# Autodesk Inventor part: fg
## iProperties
Shininess: 64.0
Length Units: 11269
Angle Units: 11279
Time Units: 11290
Mass Units: 11283
Length Display Precision: 3
Angle Display Precision: 2
Compacted: True
Part Number: fg
Document SubType Name: Modeling
Created: 2004-12
Designer: Administrator
Manufacturer: Standard
Standards Organization: Custom
Material: Aluminum-6061-AHC
Density: 0.0
Volumn: 0.0
Area: 0.0
PropertySet Name: Model Information
Control State: 0
Master: False
Checked Out: False
Author: Administrator
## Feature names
1. Extrusion1
2. Hole1
3. Fillet1
4. Extrusion2
5. Extrusion3
6. Extrusion4
7. Extrusion5
8. Fillet2
